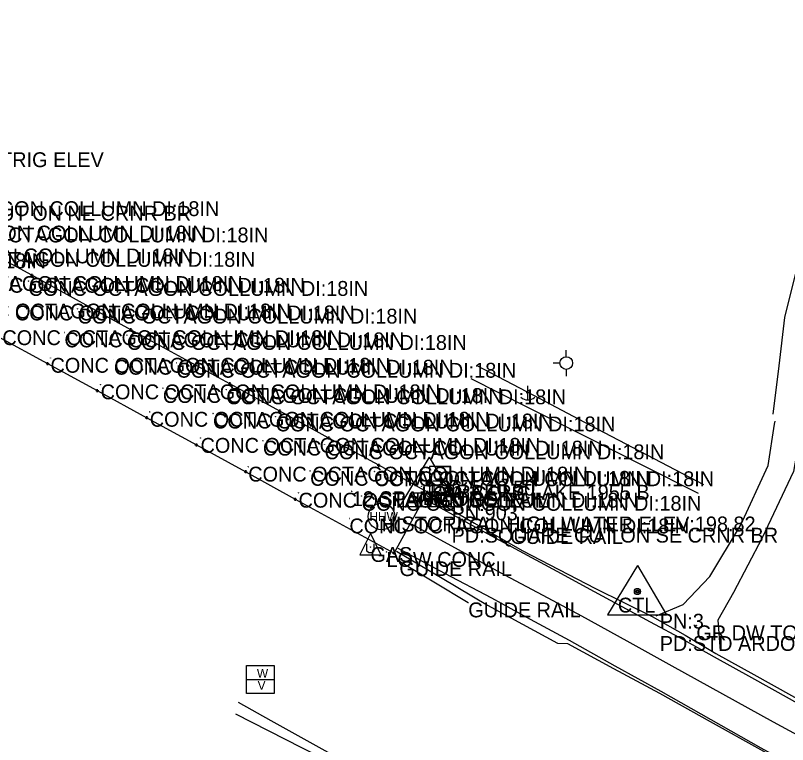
# Model space of a CAD drawing. Extents: x 1411444 to 1458157, y 300965 to 327300.
# Drawn here: x 1454797 to 1455057, y 302619.4 to 302864.8 of the extents above; entities that cross this region are included whole.
import ezdxf

# ---------------------------------------------------------------- set-up
doc = ezdxf.new("R2010")
doc.units = 0
for name, color, linetype in [('S_BRIDGE', 7, 'Continuous'), ('S_DITCHLINE', 7, 'Continuous'), ('S_DRIVEWAY', 7, 'Continuous'), ('S_EDGE_PAVEMENT', 7, 'Continuous'), ('S_GRAVEL_ROAD', 7, 'Continuous'), ('S_GUARDRAIL', 7, 'Continuous'), ('S_GUARDRAIL_ANNOT', 7, 'Continuous'), ('S_HIST_HIGH_WATER', 7, 'Continuous'), ('S_HIST_HIGH_WATER_ANNOT', 7, 'Continuous'), ('S_LOG_MILE', 7, 'Continuous'), ('S_LOG_MILE_ANNOT', 7, 'Continuous'), ('S_MISC_STRUCTURES_ANNOT', 7, 'Continuous'), ('S_MSC_PT_SYM', 7, 'Continuous'), ('S_PAVEMENT_CROWN', 7, 'Continuous'), ('S_PRIMARY_CTL', 7, 'Continuous'), ('S_PRIMARY_CTL_ANNOT', 7, 'Continuous'), ('S_RDW_PT_SYM', 7, 'Continuous'), ('S_SECONDARY_CTL_ANNOT', 7, 'Continuous'), ('S_SHOULDER', 7, 'Continuous'), ('S_STR_PT_SYM', 7, 'Continuous'), ('S_SURVEY_TEXT_ANNOT', 7, 'Continuous'), ('S_UTILITY_POLE', 7, 'Continuous'), ('S_UTILITY_POLE_ANNOT', 7, 'Continuous'), ('S_UTL_PT_SYM', 7, 'Continuous'), ('S_WATER_UTILITIES', 7, 'Continuous')]:
    doc.layers.add(name, color=color, linetype=linetype)

msp = doc.modelspace()

# ---------------------------------------------------------------- linework, layer by layer
at = {"layer": 'S_BRIDGE'}
for p, q in [((1454802.52, 302777.39), (1454785.69, 302786.53)), ((1454835.86, 302759.06), (1454802.52, 302777.39)), ((1454869.18, 302740.88), (1454835.86, 302759.06)), ((1454791.19, 302756.67), (1454807.79, 302747.62)), ((1454807.79, 302747.62), (1454824.52, 302738.54)), ((1454885.99, 302731.68), (1454869.18, 302740.88)), ((1454824.52, 302738.54), (1454841.18, 302729.41)), ((1454841.18, 302729.41), (1454857.94, 302720.24)), ((1454902.57, 302722.59), (1454885.99, 302731.68)), ((1454919.32, 302713.41), (1454902.57, 302722.59)), ((1454857.94, 302720.24), (1454874.52, 302711.22)), ((1454874.52, 302711.22), (1454891.2, 302701.99)), ((1454935.81, 302704.36), (1454919.32, 302713.41)), ((1454924.51, 302683.83), (1454935.81, 302704.36)), ((1454891.2, 302701.99), (1454924.51, 302683.83))]:
    msp.add_line(p, q, dxfattribs=at)
at = {"layer": 'S_DITCHLINE'}
for points in [[(1454952.39, 302747.02), (1454971.47, 302736.99), (1454990.55, 302726.96), (1455009.63, 302716.92), (1455028.72, 302706.89)], [(1454950.3, 302742.57), (1454969.44, 302732.92), (1454988.59, 302723.27), (1455007.73, 302713.62), (1455026.87, 302703.97)], [(1454871.95, 302633.66), (1454883.03, 302627.47), (1454894.11, 302621.28), (1454905.18, 302615.1), (1454916.26, 302608.91), (1454928.01, 302603.37), (1454939.77, 302597.83), (1454951.52, 302592.28), (1454963.28, 302586.74), (1454975.03, 302581.19), (1454986.79, 302575.65), (1454998.54, 302570.1), (1455010.3, 302564.56), (1455028.48, 302555.45), (1455046.66, 302546.34), (1455064.84, 302537.24), (1455083.02, 302528.13), (1455097.29, 302520.44), (1455111.57, 302512.75), (1455125.84, 302505.06), (1455140.12, 302497.37)], [(1454871.09, 302629.69), (1454893.36, 302618.43), (1454915.62, 302607.16), (1454927.34, 302601.38), (1454939.06, 302595.59), (1454950.79, 302589.81), (1454962.51, 302584.02), (1454974.23, 302578.24), (1454985.95, 302572.46), (1454997.67, 302566.67), (1455009.39, 302560.89), (1455027.12, 302551.71), (1455044.86, 302542.53), (1455062.59, 302533.36), (1455080.32, 302524.18), (1455095.14, 302517.17), (1455109.97, 302510.16), (1455124.79, 302503.15), (1455139.61, 302496.15)]]:
    msp.add_lwpolyline(points, dxfattribs=at)
at = {"layer": 'S_DRIVEWAY'}
for points in [[(1455012.79, 302662.7), (1455021.82, 302666.51), (1455030.79, 302675.99), (1455041.2, 302693.09), (1455050.45, 302713.39), (1455052.64, 302727.3), (1455052.79, 302728.29)], [(1455061.57, 302725.99), (1455061.5, 302725.58), (1455059.01, 302711.26), (1455048.51, 302688.93), (1455038.77, 302670.56), (1455033.52, 302661.31), (1455034.27, 302650.9)]]:
    msp.add_lwpolyline(points, dxfattribs=at)
at = {"layer": 'S_EDGE_PAVEMENT'}
for points in [[(1454934.83, 302701.99), (1454950.72, 302693.28), (1454966.61, 302684.56), (1454979.27, 302677.76), (1454991.93, 302670.96), (1455010.69, 302660.75), (1455022.05, 302654.61), (1455032.26, 302648.98), (1455044.91, 302641.94), (1455057.55, 302634.91), (1455076.23, 302624.51), (1455080.5, 302622.13)], [(1454925.81, 302685.46), (1454941.53, 302677.1), (1454957.26, 302668.74), (1454970.34, 302661.62), (1454983.42, 302654.5), (1454998.88, 302645.92), (1455014.34, 302637.35), (1455031.19, 302627.81), (1455048.04, 302618.28), (1455067.2, 302607.72), (1455069.22, 302606.61)]]:
    msp.add_lwpolyline(points, dxfattribs=at)
at = {"layer": 'S_GRAVEL_ROAD'}
msp.add_lwpolyline([(1455052.17, 302730.63), (1455054.14, 302746.92), (1455056.11, 302763.21), (1455060.56, 302781.24), (1455065.01, 302799.27), (1455071.31, 302812.73), (1455077.6, 302826.18), (1455083.9, 302839.64), (1455090.19, 302853.09), (1455097.56, 302866.95), (1455104.93, 302880.82)], dxfattribs=at)
at = {"layer": 'S_GUARDRAIL'}
msp.add_line((1454926.29, 302681.11), (1454949.48, 302667.22), dxfattribs=at)
at = {"layer": 'S_HIST_HIGH_WATER'}
msp.add_circle((1454920.28, 302696.15), 4.5, dxfattribs=at)
at = {"layer": 'S_LOG_MILE'}
for p, q in [((1454940.03, 302712.99), (1454943.63, 302712.99)), ((1454937.63, 302708.19), (1454942.43, 302708.19)), ((1454940.03, 302703.39), (1454936.43, 302703.39))]:
    msp.add_line(p, q, dxfattribs=at)
msp.add_lwpolyline([(1454943.63, 302712.99), (1454936.43, 302712.99), (1454936.43, 302703.39), (1454943.63, 302703.39)], close=True, dxfattribs=at)
at = {"layer": 'S_MSC_PT_SYM'}
for points in [[(1454801.36, 302775.44), (1454801.36, 302775.49), (1454801.36, 302775.44), (1454801.31, 302775.44), (1454801.36, 302775.44), (1454801.36, 302775.39), (1454801.36, 302775.44), (1454801.41, 302775.44)], [(1454817.9, 302766.11), (1454817.9, 302766.16), (1454817.9, 302766.11), (1454817.85, 302766.11), (1454817.9, 302766.11), (1454817.9, 302766.06), (1454817.9, 302766.11), (1454817.95, 302766.11)], [(1454813.48, 302758.11), (1454813.48, 302758.16), (1454813.48, 302758.11), (1454813.43, 302758.11), (1454813.48, 302758.11), (1454813.48, 302758.06), (1454813.48, 302758.11), (1454813.53, 302758.11)], [(1454834.55, 302757.25), (1454834.55, 302757.3), (1454834.55, 302757.25), (1454834.5, 302757.25), (1454834.55, 302757.25), (1454834.55, 302757.2), (1454834.55, 302757.25), (1454834.6, 302757.25)], [(1454808.79, 302749.56), (1454808.79, 302749.61), (1454808.79, 302749.56), (1454808.74, 302749.56), (1454808.79, 302749.56), (1454808.79, 302749.51), (1454808.79, 302749.56), (1454808.84, 302749.56)], [(1454830.12, 302748.91), (1454830.12, 302748.96), (1454830.12, 302748.91), (1454830.07, 302748.91), (1454830.12, 302748.91), (1454830.12, 302748.86), (1454830.12, 302748.91), (1454830.17, 302748.91)], [(1454851.18, 302747.89), (1454851.18, 302747.94), (1454851.18, 302747.89), (1454851.13, 302747.89), (1454851.18, 302747.89), (1454851.18, 302747.84), (1454851.18, 302747.89), (1454851.23, 302747.89)], [(1454825.68, 302740.62), (1454825.68, 302740.67), (1454825.68, 302740.62), (1454825.63, 302740.62), (1454825.68, 302740.62), (1454825.68, 302740.57), (1454825.68, 302740.62), (1454825.73, 302740.62)], [(1454846.63, 302739.4), (1454846.63, 302739.45), (1454846.63, 302739.4), (1454846.58, 302739.4), (1454846.63, 302739.4), (1454846.63, 302739.35), (1454846.63, 302739.4), (1454846.68, 302739.4)], [(1454868, 302738.94), (1454868, 302738.99), (1454868, 302738.94), (1454867.95, 302738.94), (1454868, 302738.94), (1454868, 302738.89), (1454868, 302738.94), (1454868.05, 302738.94)], [(1454842.22, 302731.39), (1454842.22, 302731.44), (1454842.22, 302731.39), (1454842.17, 302731.39), (1454842.22, 302731.39), (1454842.22, 302731.34), (1454842.22, 302731.39), (1454842.27, 302731.39)], [(1454863.52, 302730.79), (1454863.52, 302730.84), (1454863.52, 302730.79), (1454863.47, 302730.79), (1454863.52, 302730.79), (1454863.52, 302730.74), (1454863.52, 302730.79), (1454863.57, 302730.79)], [(1454884.62, 302729.82), (1454884.62, 302729.86), (1454884.62, 302729.82), (1454884.57, 302729.82), (1454884.62, 302729.82), (1454884.62, 302729.77), (1454884.62, 302729.82), (1454884.67, 302729.82)], [(1454859.32, 302722.61), (1454859.32, 302722.66), (1454859.32, 302722.61), (1454859.27, 302722.61), (1454859.32, 302722.61), (1454859.32, 302722.56), (1454859.32, 302722.61), (1454859.37, 302722.61)], [(1454880.31, 302721.68), (1454880.31, 302721.73), (1454880.31, 302721.68), (1454880.26, 302721.68), (1454880.31, 302721.68), (1454880.31, 302721.63), (1454880.31, 302721.68), (1454880.36, 302721.68)], [(1454901.07, 302720.44), (1454901.07, 302720.49), (1454901.07, 302720.44), (1454901.02, 302720.44), (1454901.07, 302720.44), (1454901.07, 302720.39), (1454901.07, 302720.44), (1454901.12, 302720.44)], [(1454875.38, 302712.93), (1454875.38, 302712.98), (1454875.38, 302712.93), (1454875.33, 302712.93), (1454875.38, 302712.93), (1454875.38, 302712.88), (1454875.38, 302712.93), (1454875.43, 302712.93)], [(1454896.22, 302711.51), (1454896.22, 302711.56), (1454896.22, 302711.51), (1454896.17, 302711.51), (1454896.22, 302711.51), (1454896.22, 302711.46), (1454896.22, 302711.51), (1454896.27, 302711.51)], [(1454917.85, 302711.37), (1454917.85, 302711.42), (1454917.85, 302711.37), (1454917.8, 302711.37), (1454917.85, 302711.37), (1454917.85, 302711.32), (1454917.85, 302711.37), (1454917.9, 302711.37)], [(1454933.74, 302706.36), (1454933.74, 302706.41), (1454933.74, 302706.36), (1454933.69, 302706.36), (1454933.74, 302706.36), (1454933.74, 302706.31), (1454933.74, 302706.36), (1454933.79, 302706.36)], [(1454936.6, 302706.83), (1454936.6, 302706.88), (1454936.6, 302706.83), (1454936.55, 302706.83), (1454936.6, 302706.83), (1454936.6, 302706.78), (1454936.6, 302706.83), (1454936.65, 302706.83)], [(1454892.33, 302704.15), (1454892.33, 302704.2), (1454892.33, 302704.15), (1454892.28, 302704.15), (1454892.33, 302704.15), (1454892.33, 302704.1), (1454892.33, 302704.15), (1454892.38, 302704.15)], [(1454910.25, 302704.65), (1454910.25, 302704.7), (1454910.25, 302704.65), (1454910.2, 302704.65), (1454910.25, 302704.65), (1454910.25, 302704.6), (1454910.25, 302704.65), (1454910.3, 302704.65)], [(1454913.57, 302703.1), (1454913.57, 302703.15), (1454913.57, 302703.1), (1454913.52, 302703.1), (1454913.57, 302703.1), (1454913.57, 302703.05), (1454913.57, 302703.1), (1454913.62, 302703.1)], [(1454909.46, 302695.49), (1454909.46, 302695.54), (1454909.46, 302695.49), (1454909.41, 302695.49), (1454909.46, 302695.49), (1454909.46, 302695.44), (1454909.46, 302695.49), (1454909.51, 302695.49)], [(1454921.93, 302684.22), (1454921.93, 302684.27), (1454921.93, 302684.22), (1454921.88, 302684.22), (1454921.93, 302684.22), (1454921.93, 302684.17), (1454921.93, 302684.22), (1454921.98, 302684.22)], [(1455026.3, 302659.52), (1455026.3, 302659.57), (1455026.3, 302659.52), (1455026.25, 302659.52), (1455026.3, 302659.52), (1455026.3, 302659.47), (1455026.3, 302659.52), (1455026.35, 302659.52)]]:
    msp.add_lwpolyline(points, dxfattribs=at)
at = {"layer": 'S_PAVEMENT_CROWN'}
msp.add_lwpolyline([(1454930.49, 302693.61), (1454946.08, 302685.09), (1454961.67, 302676.58), (1454974.63, 302669.63), (1454987.59, 302662.69), (1455002.83, 302654.29), (1455018.06, 302645.89), (1455035.14, 302636.47), (1455052.22, 302627.05), (1455065.61, 302619.76)], dxfattribs=at)
at = {"layer": 'S_PRIMARY_CTL'}
for p, q in [((1454936.36, 302716.09), (1454926.33, 302699.57)), ((1454936.36, 302716.09), (1454946.19, 302699.57)), ((1454926.33, 302699.57), (1454946.19, 302699.57)), ((1455006.46, 302679.62), (1454996.42, 302663.11)), ((1455006.46, 302679.62), (1455016.28, 302663.11)), ((1454996.42, 302663.11), (1455016.28, 302663.11))]:
    msp.add_line(p, q, dxfattribs=at)
for centre, radius in [((1454936.36, 302707.38), 1.04), ((1454936.36, 302707.38), 0.609), ((1454936.36, 302707.38), 0.344), ((1455006.46, 302670.92), 1.04), ((1455006.46, 302670.92), 0.609), ((1455006.46, 302670.92), 0.344)]:
    msp.add_circle(centre, radius, dxfattribs=at)
at = {"layer": 'S_RDW_PT_SYM'}
for points in [[(1454938.51, 302704.17), (1454938.51, 302704.22), (1454938.51, 302704.17), (1454938.46, 302704.17), (1454938.51, 302704.17), (1454938.51, 302704.12), (1454938.51, 302704.17), (1454938.56, 302704.17)], [(1454963.64, 302691.92), (1454963.64, 302691.97), (1454963.64, 302691.92), (1454963.59, 302691.92), (1454963.64, 302691.92), (1454963.64, 302691.87), (1454963.64, 302691.92), (1454963.69, 302691.92)], [(1454926.29, 302681.11), (1454926.29, 302681.16), (1454926.29, 302681.11), (1454926.24, 302681.11), (1454926.29, 302681.11), (1454926.29, 302681.06), (1454926.29, 302681.11), (1454926.34, 302681.11)], [(1454949.48, 302667.22), (1454949.48, 302667.27), (1454949.48, 302667.22), (1454949.43, 302667.22), (1454949.48, 302667.22), (1454949.48, 302667.17), (1454949.48, 302667.22), (1454949.53, 302667.22)]]:
    msp.add_lwpolyline(points, dxfattribs=at)
at = {"layer": 'S_SHOULDER'}
for points in [[(1454935.57, 302703.19), (1454951.58, 302693.96), (1454967.59, 302684.74), (1454979.96, 302678.32), (1454992.32, 302671.89), (1455011.47, 302662.5), (1455022.58, 302656.19), (1455032.9, 302650.08), (1455045.6, 302642.98), (1455058.3, 302635.88), (1455076.92, 302625.54), (1455077.59, 302625.17)], [(1454925.29, 302684.5), (1454940.65, 302675.41), (1454956.01, 302666.32), (1454967.74, 302659.95), (1454979.48, 302653.58), (1454982.92, 302653.42), (1454998.43, 302645.04), (1455013.94, 302636.66), (1455030.95, 302627.2), (1455047.95, 302617.74), (1455067.03, 302607.19), (1455068.95, 302606.13)]]:
    msp.add_lwpolyline(points, dxfattribs=at)
at = {"layer": 'S_STR_PT_SYM'}
for points in [[(1454802.52, 302777.39), (1454802.52, 302777.89), (1454802.52, 302777.39), (1454802.02, 302777.39), (1454802.52, 302777.39), (1454802.52, 302776.89), (1454802.52, 302777.39), (1454803.02, 302777.39)], [(1454835.86, 302759.06), (1454835.86, 302759.56), (1454835.86, 302759.06), (1454835.36, 302759.06), (1454835.86, 302759.06), (1454835.86, 302758.56), (1454835.86, 302759.06), (1454836.36, 302759.06)], [(1454807.79, 302747.62), (1454807.79, 302748.12), (1454807.79, 302747.62), (1454807.29, 302747.62), (1454807.79, 302747.62), (1454807.79, 302747.12), (1454807.79, 302747.62), (1454808.29, 302747.62)], [(1454869.18, 302740.88), (1454869.18, 302741.38), (1454869.18, 302740.88), (1454868.68, 302740.88), (1454869.18, 302740.88), (1454869.18, 302740.38), (1454869.18, 302740.88), (1454869.68, 302740.88)], [(1454824.52, 302738.54), (1454824.52, 302739.04), (1454824.52, 302738.54), (1454824.02, 302738.54), (1454824.52, 302738.54), (1454824.52, 302738.04), (1454824.52, 302738.54), (1454825.02, 302738.54)], [(1454885.99, 302731.68), (1454885.99, 302732.18), (1454885.99, 302731.68), (1454885.49, 302731.68), (1454885.99, 302731.68), (1454885.99, 302731.18), (1454885.99, 302731.68), (1454886.49, 302731.68)], [(1454841.18, 302729.41), (1454841.18, 302729.91), (1454841.18, 302729.41), (1454840.68, 302729.41), (1454841.18, 302729.41), (1454841.18, 302728.91), (1454841.18, 302729.41), (1454841.68, 302729.41)], [(1454902.57, 302722.59), (1454902.57, 302723.09), (1454902.57, 302722.59), (1454902.07, 302722.59), (1454902.57, 302722.59), (1454902.57, 302722.09), (1454902.57, 302722.59), (1454903.07, 302722.59)], [(1454857.94, 302720.24), (1454857.94, 302720.74), (1454857.94, 302720.24), (1454857.44, 302720.24), (1454857.94, 302720.24), (1454857.94, 302719.74), (1454857.94, 302720.24), (1454858.44, 302720.24)], [(1454919.32, 302713.41), (1454919.32, 302713.91), (1454919.32, 302713.41), (1454918.82, 302713.41), (1454919.32, 302713.41), (1454919.32, 302712.91), (1454919.32, 302713.41), (1454919.82, 302713.41)], [(1454874.52, 302711.22), (1454874.52, 302711.72), (1454874.52, 302711.22), (1454874.02, 302711.22), (1454874.52, 302711.22), (1454874.52, 302710.72), (1454874.52, 302711.22), (1454875.02, 302711.22)], [(1454935.81, 302704.36), (1454935.81, 302704.86), (1454935.81, 302704.36), (1454935.31, 302704.36), (1454935.81, 302704.36), (1454935.81, 302703.86), (1454935.81, 302704.36), (1454936.31, 302704.36)], [(1454891.2, 302701.99), (1454891.2, 302702.49), (1454891.2, 302701.99), (1454890.7, 302701.99), (1454891.2, 302701.99), (1454891.2, 302701.49), (1454891.2, 302701.99), (1454891.7, 302701.99)], [(1454924.51, 302683.83), (1454924.51, 302684.33), (1454924.51, 302683.83), (1454924.01, 302683.83), (1454924.51, 302683.83), (1454924.51, 302683.33), (1454924.51, 302683.83), (1454925.01, 302683.83)]]:
    msp.add_lwpolyline(points, dxfattribs=at)
at = {"layer": 'S_UTILITY_POLE'}
for p, q in [((1454982.5, 302749.91), (1454982.5, 302752.16)), ((1454980.41, 302747.78), (1454978.08, 302747.78)), ((1454982.58, 302743.36), (1454982.58, 302745.69)), ((1454969.48, 302740.1), (1454969.48, 302735.37)), ((1454916.55, 302690.4), (1454913.02, 302683.31)), ((1454916.55, 302690.4), (1454920.03, 302683.31)), ((1454915.35, 302684.55), (1454915.35, 302686.99)), ((1454917.71, 302686.99), (1454917.71, 302684.55)), ((1454913.02, 302683.31), (1454920.03, 302683.31)), ((1454915.97, 302683.89), (1454915.35, 302684.55)), ((1454917.17, 302683.89), (1454915.97, 302683.89)), ((1454917.71, 302684.55), (1454917.17, 302683.89))]:
    msp.add_line(p, q, dxfattribs=at)
msp.add_circle((1454982.5, 302747.8), 2.13, dxfattribs=at)
msp.add_arc((1454969.54, 302738.8), 3.41, 226.3972, 313.6028, dxfattribs=at)
at = {"layer": 'S_UTL_PT_SYM'}
msp.add_lwpolyline([(1454916.53, 302685.88), (1454916.53, 302685.93), (1454916.53, 302685.88), (1454916.48, 302685.88), (1454916.53, 302685.88), (1454916.53, 302685.83), (1454916.53, 302685.88), (1454916.58, 302685.88)], dxfattribs=at)
at = {"layer": 'S_WATER_UTILITIES'}
for p, q in [((1454874.75, 302646.04), (1454884.17, 302646.04)), ((1454874.75, 302636.63), (1454874.75, 302646.04)), ((1454884.17, 302646.04), (1454884.17, 302636.63)), ((1454874.75, 302641.35), (1454884.17, 302641.35)), ((1454884.17, 302636.63), (1454874.75, 302636.63))]:
    msp.add_line(p, q, dxfattribs=at)

# ---------------------------------------------------------------- texts
at = {"layer": 'S_GUARDRAIL_ANNOT'}
for p in [(1454938.51, 302699.17), (1454963.64, 302686.92), (1454926.29, 302676.11), (1454949.48, 302662.22)]:
    msp.add_text('GUIDE RAIL', height=5, dxfattribs=at).set_placement(p)
at = {"layer": 'S_HIST_HIGH_WATER'}
msp.add_text('HHW', height=3, rotation=360, dxfattribs=at).set_placement((1454916.2, 302694.65))
at = {"layer": 'S_HIST_HIGH_WATER_ANNOT'}
msp.add_text('HISTORICAL HIGH WATER ELEV:198.82', height=5, dxfattribs=at).set_placement((1454920.28, 302691.15))
at = {"layer": 'S_LOG_MILE'}
msp.add_text('LM', height=3, rotation=360, dxfattribs=at).set_placement((1454937.49, 302704.35))
at = {"layer": 'S_LOG_MILE_ANNOT'}
msp.add_text('36-5 10.50', height=5, dxfattribs=at).set_placement((1454940.03, 302703.19))
at = {"layer": 'S_MISC_STRUCTURES_ANNOT'}
for s, p in [('CONC OCTAGON COLLUMN DI:18IN', (1454751.22, 302797.29)), ('CONC OCTAGON COLLUMN DI:18IN', (1454746.92, 302789.07)), ('CONC OCTAGON COLLUMN DI:18IN', (1454767.76, 302788.44)), ('CONC OCTAGON COLLUMN DI:18IN', (1454742.48, 302781.38)), ('CONC OCTAGON COLLUMN DI:18IN', (1454763.29, 302780.22)), ('DI:18IN', (1454784.63, 302779.73)), ('CONC OCTAGON COLLUMN DI:18IN', (1454759.04, 302772.08)), ('CONC OCTAGON COLLUMN DI:18IN', (1454780.02, 302771.5)), ('CONC OCTAGON COLLUMN DI:18IN', (1454801.36, 302770.44)), ('CONC OCTAGON COLLUMN DI:18IN', (1454775.32, 302762.82)), ('CONC OCTAGON COLLUMN DI:18IN', (1454796.79, 302762.18)), ('CONC OCTAGON COLLUMN DI:18IN', (1454817.9, 302761.11)), ('CONC OCTAGON COLLUMN DI:18IN', (1454792.58, 302753.86)), ('CONC OCTAGON COLLUMN DI:18IN', (1454813.48, 302753.11)), ('CONC OCTAGON COLLUMN DI:18IN', (1454834.55, 302752.25)), ('CONC OCTAGON COLLUMN DI:18IN', (1454808.79, 302744.56)), ('CONC OCTAGON COLLUMN DI:18IN', (1454830.12, 302743.91)), ('CONC OCTAGON COLLUMN DI:18IN', (1454851.18, 302742.89)), ('CONC OCTAGON COLLUMN DI:18IN', (1454825.68, 302735.62)), ('CONC OCTAGON COLLUMN DI:18IN', (1454846.63, 302734.4)), ('CONC OCTAGON COLLUMN DI:18IN', (1454868, 302733.94)), ('CONC OCTAGON COLLUMN DI:18IN', (1454842.22, 302726.39)), ('CONC OCTAGON COLLUMN DI:18IN', (1454863.52, 302725.79)), ('CONC OCTAGON COLLUMN DI:18IN', (1454884.62, 302724.82)), ('CONC OCTAGON COLLUMN DI:18IN', (1454859.32, 302717.61)), ('CONC OCTAGON COLLUMN DI:18IN', (1454880.31, 302716.68)), ('CONC OCTAGON COLLUMN DI:18IN', (1454901.07, 302715.44)), ('CONC OCTAGON COLLUMN DI:18IN', (1454875.38, 302707.93)), ('CONC OCTAGON COLLUMN DI:18IN', (1454896.22, 302706.51)), ('CONC OCTAGON COLLUMN DI:18IN', (1454917.85, 302706.37)), ('CONC OCTAGON COLLUMN DI:18IN', (1454892.33, 302699.15)), ('CONC OCTAGON COLLUMN DI:18IN', (1454913.57, 302698.1)), ('CONC OCTAGON COLLUMN DI:18IN', (1454909.46, 302690.49))]:
    msp.add_text(s, height=5, dxfattribs=at).set_placement(p)
at = {"layer": 'S_PRIMARY_CTL'}
for s, height, p in [('TBM', 4.287, (1454930.71, 302700)), ('CTL', 5, (1454999.87, 302663.84))]:
    msp.add_text(s, height=height, rotation=360, dxfattribs=at).set_placement(p)
at = {"layer": 'S_PRIMARY_CTL_ANNOT'}
for s, p in [('PD:SQUARE CUT ON NE CRNR BR', (1454745.79, 302795.75)), ('PN:903', (1454943.86, 302694.88)), ('PD:SQUARE CUT ON SE CRNR BR', (1454943.86, 302687.38)), ('PN:3', (1455013.96, 302658.42)), ('PD:STD ARDOT CAP STAMPED PN:3', (1455013.96, 302650.92))]:
    msp.add_text(s, height=5, dxfattribs=at).set_placement(p)
at = {"layer": 'S_SECONDARY_CTL_ANNOT'}
msp.add_text('PD:8 SPIKE TRIG ELEV', height=5, dxfattribs=at).set_placement((1454753.54, 302813.77))
at = {"layer": 'S_SURVEY_TEXT_ANNOT'}
for s, p in [('LOW CONC', (1454933.74, 302701.36)), ('BARBERS LAKE 1955 B', (1454936.6, 302701.83)), ('12 SPAN CONC', (1454910.25, 302699.65)), ('LOW CONC', (1454921.93, 302679.22)), ('GR DW TO FIELD', (1455026.3, 302654.52))]:
    msp.add_text(s, height=5, dxfattribs=at).set_placement(p)
at = {"layer": 'S_UTILITY_POLE_ANNOT'}
msp.add_text('GAS', height=5, dxfattribs=at).set_placement((1454916.55, 302680.87))
at = {"layer": 'S_WATER_UTILITIES'}
for s, p in [('W', (1454878.3, 302641.88)), ('V', (1454878.54, 302637.82))]:
    msp.add_text(s, height=3, rotation=360, dxfattribs=at).set_placement(p)

doc.saveas('drawing.dxf')
